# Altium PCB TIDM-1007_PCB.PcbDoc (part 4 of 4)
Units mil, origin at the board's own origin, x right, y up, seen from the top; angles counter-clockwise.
Board outline 9645.67 x 3346.46 mil, 6 copper layers (Top Layer, Signal Layer 1, Signal Layer 2, Signal Layer 3, Signal Layer 4, Bottom Layer), stack 60.2 mil thick; 189 components, 109 nets, 620 pads, 278 vias.
Unrouted connection lines stored in the file: 5.
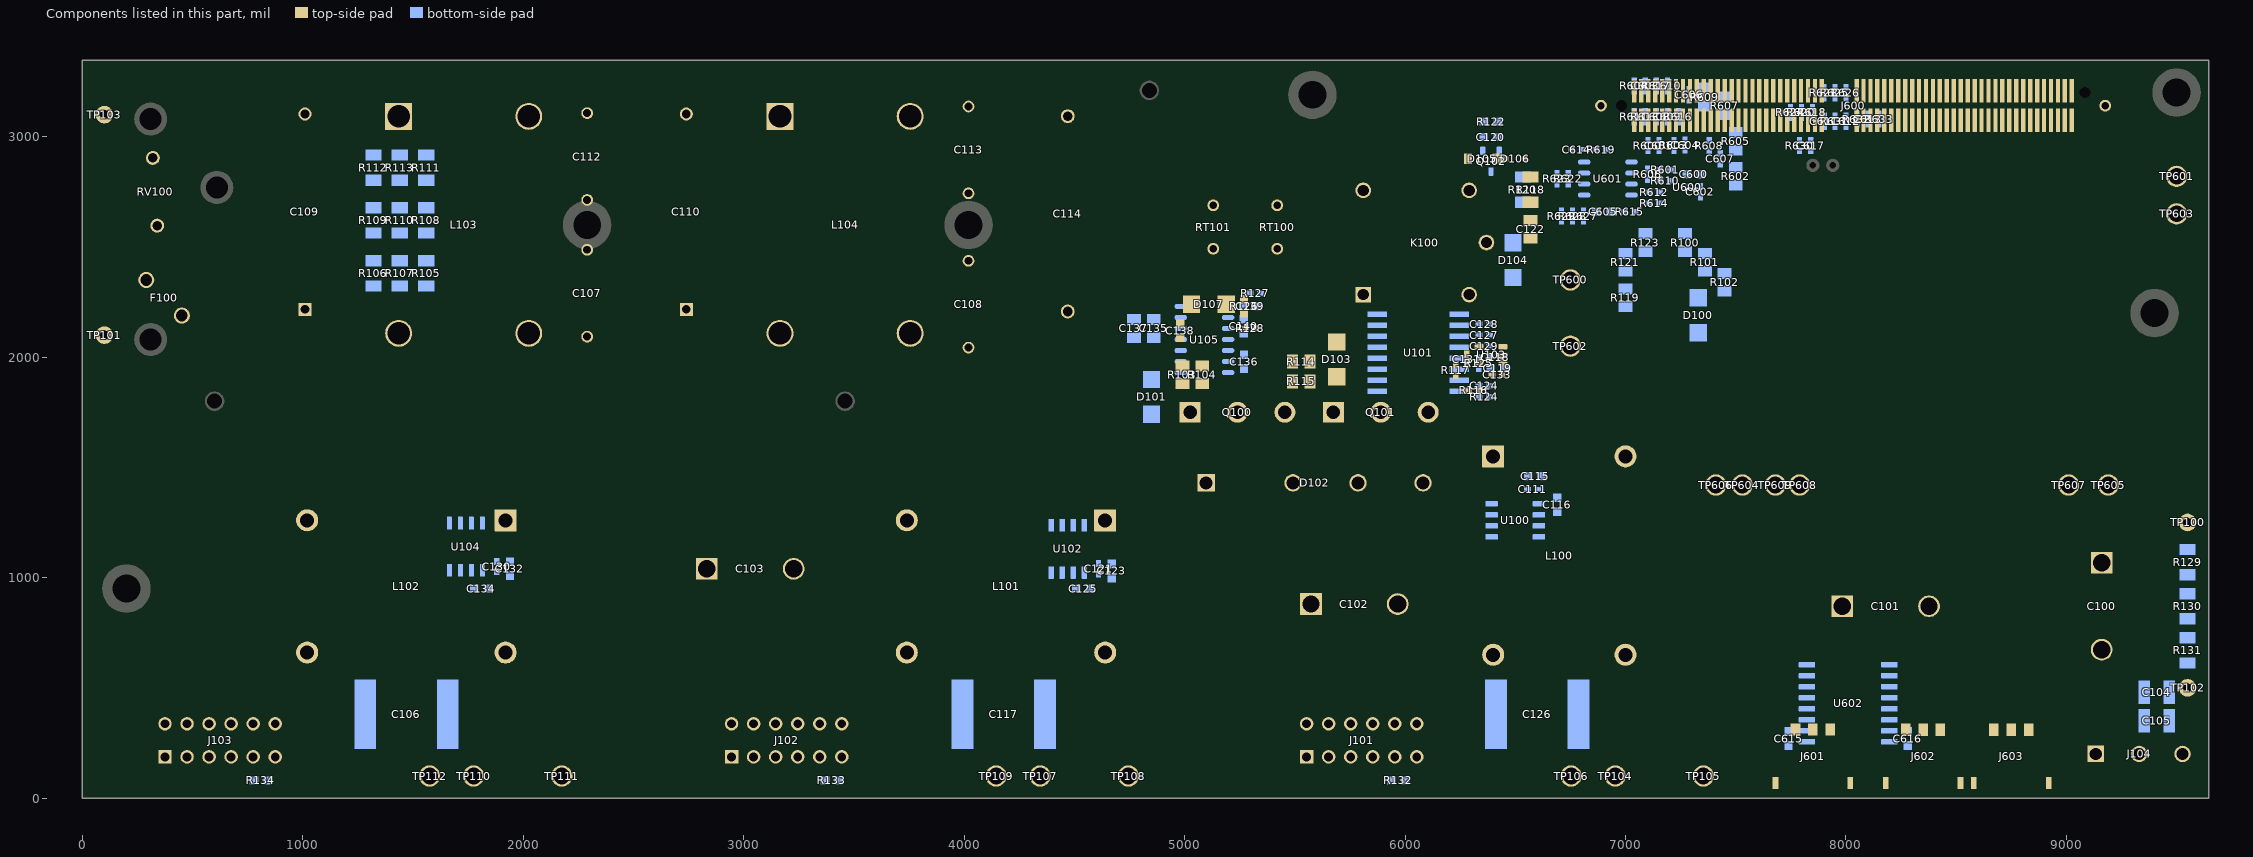
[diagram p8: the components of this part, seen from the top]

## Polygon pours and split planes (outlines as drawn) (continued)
PGND on Signal Layer 4 "PGND" (solid, remove dead copper, pour order 244): 75 vertices, not listed, extent 260,20 9630,3330
NetL102_1 on Signal Layer 4 "L102_1" (solid, remove dead copper, pour order 192): 1770,1200.32 1750,1220.32 1750,1230.32 1750,1260.32 1750,1400 1770,1420 1930,1420 1980,1370 1980,1220.32 1960,1200.32
NetL101_1 on Signal Layer 4 "L101_1" (solid, remove dead copper, pour order 220): 4500,1190 4480,1210 4480,1230 4480,1370 4500,1390 4630,1390 4700,1320 4700,1210 4680,1190
NetL100_1 on Signal Layer 4 "L100_1" (solid, remove dead copper, pour order 228): 6430,1270 6450,1290 6450,1340 6450,1430 6450,1490 6470,1510 6470,1590 6450,1610 6350,1610 6330,1610 6260,1540 6260,1290 6280,1270
SGND2 on Bottom Layer "SGND2" (solid, remove dead copper, pour order 162): 20 vertices, not listed, extent 8160,10 8860,620
NetC109_2 on Bottom Layer "C109_2" (solid, remove dead copper, pour order 16): 20 vertices, not listed, extent 50,2870 1620,3300
NetC110_2 on Bottom Layer "C110_2" (solid, remove dead copper, pour order 22): 1970,3020 1960,3030 1960,3050 1960,3160 2020,3220 2100,3300 2140,3300 3100,3300 3240,3160 3240,3130 3240,3030 3230,3020
-BRDG_N on Bottom Layer "-BRDG_N" (solid, remove dead copper, pour order 64): 29 vertices, not listed, extent 5400,1380 5990,2010
NetF100_2 on Bottom Layer "F100_2" (solid, remove dead copper, pour order 72): 50,2000 110,1940 330,1940 360,1940 500,2080 500,2120 500,2200 470,2230 420,2230 160,2230 50,2120
NetC109_1 on Bottom Layer "C109_1" (solid, remove dead copper, pour order 84): 260.56,2630 140,2509.44 140,2270 160,2250 230,2250 470,2250 580,2140 680,2040 1410,2040 1580,2040 1600,2060 1600,2320 1580,2340 670,2340 380,2630
NetC107_1 on Bottom Layer "C107_1" (solid, remove dead copper, pour order 100): 1960,1950 1970,1940 3230,1940 3240,1950 3240,2130 3100,2270 3050,2270 2550,2270 2460,2180 2270,2180 1970,2180 1960,2170
EARTH on Bottom Layer "Earth" (solid, remove dead copper, pour order 122): 19 vertices, not listed, extent 2140,2390 4140,2800
NetL102_1 on Bottom Layer "L102_1" (solid, remove dead copper, pour order 142): 1770,1200.32 1750,1220.32 1750,1230.32 1750,1260.32 1750,1400 1770,1420 1930,1420 1980,1370 1980,1220.32 1960,1200.32
NetL101_1 on Bottom Layer "L101_1" (solid, remove dead copper, pour order 146): 4500,1190 4480,1210 4480,1230 4480,1370 4500,1390 4630,1390 4700,1320 4700,1210 4680,1190
NetL100_1 on Bottom Layer "L100_1" (solid, remove dead copper, pour order 154): 6430,1270 6450,1290 6450,1340 6450,1430 6450,1490 6470,1510 6470,1590 6450,1610 6350,1610 6330,1610 6260,1540 6260,1290 6280,1270
NetC113_1 on Bottom Layer "C113_2" (solid, remove dead copper, pour order 166): 3700,3020 3690,3030 3690,3060 3690,3160 3830,3300 4405.28,3300 4825.28,2880 5800,2880 5870,2810 5870,2780 5870,2660 5850,2640 5620,2640 4560,2640 4180,3020
AC_L on Bottom Layer "AC_L" (solid, remove dead copper, pour order 176): 66 vertices, not listed, extent 1440,1020 6450,2270
AC_N on Bottom Layer "AC_N" (solid, remove dead copper, pour order 180): 23 vertices, not listed, extent 4870,2030 6410,2620
HVBUS on Bottom Layer "HVBUS" (solid, remove dead copper, pour order 234): 26 vertices, not listed, extent 7820,140 9630,1300
EARTH on Bottom Layer "EARTH" (solid, remove dead copper, pour order 238): 18 vertices, not listed, extent 10,780 670,1850
PGND on Bottom Layer "PGND" (solid, remove dead copper, pour order 242): 64 vertices, not listed, extent 260,20 9630,3330
EARTH on Bottom Layer "EARTH" (solid, remove dead copper, pour order 254): 9290,2740 9290,2070 9310,2050 9620,2050 9640,2070 9640,2090 9640,2470 9640,2740 9620,2760 9310,2760

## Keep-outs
Keep-Out Layer:
  text ".Layer_Name" at 577,-858.49 h60

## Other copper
Top Layer:
  text ".Layer_Name" at 577,-858.49 h60
Bottom Layer:
  text ".Layer_Name" at 577,-858.49 h60

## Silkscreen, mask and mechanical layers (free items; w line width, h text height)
Top Overlay:
  lines w7: 4930,2160 4930,2900 5560,2900 5560,2100 5380,2100 ; 5580,2100 5580,2900 6210,2900 6210,2100 6000,2100 ; 6650,2950 6650,1822.74 7162.26,1822.74 7162.26,1350 9650,1350 9650,2950 8000,2950 ; 6760,2950 7500,2950
  lines w10: 40,1660 130,1660 150,1680 ; 1880,1890 1940,1830 ; 2420,2600 2550,2600 2720,2770 2830,2770 3210,2770 3290,2850 ; 3530,2850 3690,2690 3890,2690 3910,2670 ; 4990,2010 5010,2030 5130,2030 ; 4990,3210 4990,3300 ; 6490,2490 6490,2670 6500,2680 ; 20,1500 20,1830 4810,1830 4810,3320 5090,3320 5090,3300 4830,3300 4830,1810 40,1810 40,1500 20,1500 ; 310,0 2280,0 2280,250 310,250 310,0 ; 2880,0 2880,250 4850,250 4850,0 2880,0 ; 5488.45,-0.23 5488.45,249.77 7458.45,249.77 7458.45,-0.23 5488.45,-0.23
  text "Clearance: L to N >2mm. L/N to PE: 5mm. PGND to SGND: 5mm." at 210,3280 h72.83
  text "Screw / to  / case / here" at 4890,3000 h72.83
  text "Board cutout for Q100 and Q101 clip screw." at 4950,2930 h72.83
  text "Screw to bottom heatsink / #4-40" at 3100,2889.22 h72.83
  text "Grounded Heatsink with 0.5mm thickness." at 60,1870 h100
  text "Reserved for Bias Supply daughter board. No power components on top side." at 7300,1680 h72.83
  text "Screw to case here" at 170,1670 h100
  text ".Layer_Name" at 577,-858.49 h60
Bottom Overlay:
  lines w10: 1080,2640 1240,2640 ; 1890,990 1890,960 1930,920 ; 5380,2220 5420,2180 5430,2180 ; 6510,1960 6600,1960 ; 6610,2570 6610,2680 6670,2740 6680,2740 6690,2750 ; 6650,1410 6690,1410 6710,1430 6760,1430 ; 6660,2570 6660,2700 6680,2720 6720,2720 6740,2740 6740,2750 ; 6670,1460 6690,1460 6720,1490 6750,1490 ; 6690,2030 6600,2030 6600,1890 6810,1890 6830,1890 6830,2030 6810,2030 ; 7340,2660 7390,2610 7620,2610 7750,2480 ; 7900,3150 7920,3150 ; 8200,3070 8340,3070 ; 790,2270 1080,2270 1080,2980 790,2980 790,2870 790,2270 ; 7720,1840 7840,1720 8170,1720 8270,1820 8270,2420 8180,2510 7780,2510 7720,2450 7720,1840 ; 8340,2830 8490,2680 8770,2680 8840,2750 8840,3140 8790,3190 8430,3190 8340,3100 8340,2830
  text ".Layer_Name" at 577,-858.49 h60
Top Paste:
  text ".Layer_Name" at 577,-858.49 h60
Bottom Paste:
  text ".Layer_Name" at 577,-858.49 h60
Top Solder:
  text ".Layer_Name" at 577,-858.49 h60
  text ".Layer_Name" at 577,-858.49 h60
Bottom Solder:
  rectangle: 4950,1150 5300,1290
  rectangle: 4280,1410 4750,1540
  rectangle: 3030,1450 3390,1690
  text ".Layer_Name" at 577,-858.49 h60
Drill Guide:
  text ".Layer_Name" at 577,-858.49 h60
M1 Board Outline:
  the board outline again, w7.01
  text ".Layer_Name" at 577,-858.49 h60
M2 Board Dimensions:
  rectangle: 0,-275 125,-150
  rectangle: 125,-400 500,-275
  lines w7: 0,-275 1000,-275 ; 125,-400 125,-150 ; 250,-400 250,-150 ; 500,-400 500,-150 ; 750,-400 750,-150 ; 0,-400 1000,-400 1000,-150 0,-150 0,-400
  text ".Layer_Name" at 577,-858.49 h60
M3 3D STEP Top:
  text ".Layer_Name" at 577,-858.49 h60
M4 3D STEP Bottom:
  text ".Layer_Name" at 577,-858.49 h60
M5 Assembly Top:
  lines w10: -292,-930.17 6308,-930.17 ; -292,-726.83 6310,-726.83 ; -292,-523.5 -292,-1133.5 3713,-1133.5 6310,-1133.5 6310,-523.5 -291.5,-523.5 -291.5,-1133.5 1284,-1133.5 ; 2173,-1133.5 2173,-523.5 ; 3440,-726.83 3440,-523.5 ; 4280,-726.83 4280,-523.5 ; 4902,-1140 4902,-937.17
  text "COMPONENTS MARKED 'DNP' SHOULD NOT BE POPULATED." at 1153.5,-318.5 h60
  text "ASSEMBLY VARIANT:" at 1153,-434 h60
  text ".VariantName" at 2189,-434 h60
  text "PCB VIEWED FROM TOP SIDE" at -228.5,-655.67 h60
  text "BOARD #:" at 2248,-655.67 h60
  text ".PRJ_Number" at 2793.5,-655.67 h60
  text "REV:" at 3638,-655.67 h60
  text ".PCB_Rev" at 3929.5,-655.67 h60
  text "SVN REV:" at 4476,-655.67 h60
  text ".VersionControl_RevNumber" at 4982,-655.67 h60
  text "TID #:" at 2248,-859 h60
  text ".TID" at 2793.5,-859 h60
  text "PLOT NAME =" at -228.5,-1064.34 h60
  text ".plot_File_Name" at 577,-1064.34 h60
  text "GENERATED    :" at 2250,-1064.34 h60
  text ".Print_Date" at 3119.5,-1064.34 h60
  text ".Print_Time" at 3848.5,-1064.34 h60
  text "TEXAS INSTRUMENTS" at 5113,-1064.34 h60
M6 Assembly Bottom:
  lines w10: -292.5,-727.33 6309.5,-727.33 ; -290.5,-930.67 6309.5,-930.67 ; 1115.5,-1140.5 1115.5,-937.67 ; 1737.5,-727.33 1737.5,-524 ; 2577.5,-727.33 2577.5,-524 ; 3844.5,-1134 3844.5,-524 ; 4733.5,-1134 6309,-1134 6309,-524 -292.5,-524 -292.5,-1134 2304.5,-1134 6309.5,-1134 6309.5,-524
  text "COMPONENTS MARKED 'DNP' SHOULD NOT BE POPULATED." at 6102,-318 h60
  text ".VariantName" at 5058,-434 h60
  text "ASSEMBLY VARIANT:" at 6097,-434 h60
  text ".VersionControl_RevNumber" at 1035.5,-656.17 h60
  text "SVN REV:" at 1541.5,-656.17 h60
  text ".PCB_Rev" at 2088,-656.17 h60
  text "REV:" at 2379.5,-656.17 h60
  text ".PRJ_Number" at 3224,-656.17 h60
  text "BOARD #:" at 3769.5,-656.17 h60
  text "PCB VIEWED FROM BOTTOM SIDE" at 6246,-656.17 h60
  text ".TID" at 3224,-859.5 h60
  text "TID #:" at 3769.5,-859.5 h60
  text "TEXAS INSTRUMENTS" at 904.5,-1064.84 h60
  text ".Print_Time" at 2169,-1064.84 h60
  text ".Print_Date" at 2898,-1064.84 h60
  text "GENERATED    :" at 3767.5,-1064.84 h60
  text ".plot_File_Name" at 5440.5,-1064.84 h60
  text "PLOT NAME =" at 6246,-1064.84 h60
M9 Title Sheet:
  drawing of 57 lines, arcs and shapes, not listed
  text "1" at 739.84,8036.5 h70
  text "2" at 3235.5,8036.5 h70
  text "3" at 5724.84,8036.5 h70
  text "4" at 8231.51,8036.5 h70
  text "5" at 10730.5,8036.5 h70
  text "6" at 13235.5,8036.5 h70
  text "A" at -416.5,6893.5 h70
  text "A" at 14383.5,6893.5 h70
  text "B" at -416.5,4513.5 h70
  text "B" at 14383.5,4513.5 h70
  text "C" at -416.5,2138.5 h70
  text "C" at 14383.5,2138.5 h70
  text "PROJECT TITLE:" at 11343.5,277.5 h45
  text ".PRJ_Title" at 11393.5,144.17 h70
  text "DESIGNED FOR:" at 11343.5,-23.5 h45
  text ".PRJ_Customer" at 11393.5,-163.5 h70
  text "D" at -416.5,-231.5 h70
  text "D" at 14383.5,-231.5 h70
  text "FILE NAME:" at 11343.5,-323.5 h45
  text ".PCB_File_Name_No_Path" at 11393.5,-443.5 h70
  text "Texas Instruments (TI) and/or its licensors do not warrant the accuracy or completeness of this specification" at 6374,-605.34 h45
  text "ENGINEER:" at 11343.5,-613.5 h45
  text "LAYOUT BY:" at 12848.5,-613.5 h45
  text "or any information contained therein. TI and/or its licensors do not warrant that this design will meet" at 6329.01,-718 h45
  text ".PRJ_Engineer" at 11393.5,-768.49 h70
  text ".PCB_Layout" at 12899,-768.49 h70
  text "the specifications, will be suitable for your application or fit for any particular purpose, or will operate in" at 6329.01,-830.67 h45
  text ".Layer_Name" at 577,-858.49 h60
  text "ALTIUM DESIGNER VERSION:" at 12848.5,-923.5 h45
  text "an implementation. TI and/or its licensors do not warrant that the design is production worthy. You should" at 6329.01,-943.33 h45
  text "completely validate and test your design implementation to confirm the system functionality for your application." at 6374,-1056 h45
  text ".print_Scale" at 11393.5,-1056.83 h70
  text ".Application_BuildNumber" at 12899,-1056.83 h70
  text "1" at 739.84,-1263.5 h70
  text "2" at 3235.5,-1263.5 h70
  text "3" at 5724.84,-1263.5 h70
  text "4" at 8231.51,-1263.5 h70
  text "5" at 10730.5,-1263.5 h70
  text "6" at 13235.5,-1263.5 h70
M10 Fab Notes:
  drawing of 173 lines, arcs and shapes, not listed
  text "DESIGN INFORMATION" at 12378.02,6201 h60
  text "MIN. TRACK WIDTH:" at 11733.46,6021 h60
  text "7" at 12829.7,6021 h60
  text "MIL" at 12984.46,6021 h60
  text "MIN. CLEARANCE:" at 11733.46,5889 h60
  text "0.2" at 12769.7,5889 h60
  text "mm" at 12984.46,5889 h60
  text "MIN. VIA PAD SIZE:" at 11733.46,5757 h60
  text "10" at 12799.71,5757 h60
  text "MIL" at 12984.46,5757 h60
  text "0.05mm (2MIL)" at 12428.46,5615.29 h60
  text "MINIMUM ANNULAR RING" at 11404.23,5611 h60
  text "EXTERNAL" at 13136.46,5611 h60
  text "PER" at 11604.23,5493 h60
  text "IPC-D-275 CLASS 2 LEVEL C" at 11824.23,5493 h60
  text "MIL, HOLES" at 13312.46,5380.71 h60
  text "+/-" at 12920,5380 h60
  text "+/-" at 13774,5380 h60
  text "REGISTRATION TOLERANCES:" at 11404.23,5375 h60
  text "METAL" at 12604,5375 h60
  text "5" at 13180.2,5375 h60
  text "3" at 14013.2,5375 h60
  text "MIL" at 14129.46,5375 h60
  text "+/-" at 13774,5262 h60
  text "HOLE SIZE TOLERANCE (UNLESS OTHERWISE SPECIFIED):" at 11404.23,5257 h60
  text "3" at 14013.2,5257 h60
  text "MIL" at 14129.46,5257 h60
  text "MATERIAL:" at 11329.46,5047.54 h60
  text "FR-4 High Tg" at 12315.9,4907.21 h60
  text "FR-408" at 11750.46,4898.64 h60
  text "OTHER" at 13238.46,4898.64 h60
  text "X" at 12161,4895 h60
  text "62 MIL (1.6mm) +/-10%" at 12070.56,4735.92 h60
  text "THICKNESS:" at 11404.23,4731.64 h60
  text "X" at 11942.4,4731.64 h60
  text "OTHER" at 13355.46,4731.64 h60
  text "TOLERANCE:" at 11404.23,4573.64 h60
  text "X" at 12243.53,4573.64 h60
  text "ANSI IPC-6012 TYPE 3 CLASS 2" at 12430.48,4573.64 h60
  text "OTHER +/-" at 12430.46,4417.64 h60
  text "BOW & TWIST:" at 11404.23,4260.64 h60
  text "X" at 12243.53,4260.64 h60
  text "ANSI IPC-6012 TYPE 3 CLASS 2" at 12430.48,4260.64 h60
  text "OTHER +/-" at 12430.46,4102.13 h60
  text "DRILLING:" at 11329.46,3963.64 h60
  text "REFERENCE:" at 11404.23,3846.64 h60
  text "X" at 12052.46,3846.64 h60
  text "AS SHOWN" at 12239.46,3846.64 h60
  text "X" at 12953.46,3846.64 h60
  text "NC_DRILL FILES" at 13090.46,3846.64 h60
  text "PTH COPPER THICKNESS:" at 11404.23,3688.64 h60
  text "X" at 12534.46,3688.64 h60
  text "20-30 um" at 12671.46,3688.64 h60
  text "OTHER" at 13388.46,3688.64 h60
  text "BOARD FINISH:" at 11329.46,3529.64 h60
  text "SILKSCREEN:" at 11484.68,3411.64 h60
  text "X" at 12433.46,3411.64 h60
  text "TOP" at 12559.46,3411.64 h60
  text "X" at 12943.46,3411.64 h60
  text "BOTTOM" at 13070.46,3411.64 h60
  text "SILKSCREEN COLOR:" at 11484.68,3244.64 h60
  text "X" at 12432.42,3244.64 h60
  text "WHITE" at 12559.46,3244.64 h60
  text "OTHER" at 13070.46,3244.64 h60
  text "X" at 12563.42,3085.44 h60
  text "GREEN" at 12690.46,3085.44 h60
  text "OTHER" at 13308.46,3085.44 h60
  text "SOLDER RESIST COLOR:" at 11484.68,3074.64 h60
  text "X" at 12563.42,2915.44 h60
  text "MATTE" at 12690.46,2915.44 h60
  text "SEMI-GLOSS" at 13308,2914.8 h60
  text "IMMERSION GOLD (ENIG)" at 12390.46,2726.92 h60
  text "ENEPIG" at 13728,2723.64 h60
  text "SURFACE FINISH:" at 11329.46,2722.64 h60
  text "IMM. TIN/SILVER OR EQUIV" at 11659,2565.64 h60
  text "OTHER" at 13090.46,2565.64 h60
  text "X" at 11500,2560 h60
  text "ARRAY/PANEL:" at 11329.46,2386.64 h60
  text "CUT AND TRIM PER M1 BOARD OUTLINE" at 12390.46,2382.35 h60
  text "N.C. ROUTE" at 12390.46,2230.64 h60
  text "X" at 13069.46,2230.64 h60
  text "V. SCORE" at 13256.46,2230.64 h60
  text "CERTIFICATION:" at 11329.46,2093.64 h60
  text "MATERIALS AND WORKMANSHIP FOR ALL PCBS" at 12054.46,2093.64 h60
  text "TO MEET OR EXCEED THE REQUIREMENTS OF:" at 12054.46,1995.64 h60
  text "X" at 11680.96,1859.13 h60
  text "ANSI IPC-A-600F CLASS ->" at 11819.96,1859.13 h60
  text "X" at 13459.02,1859.13 h60
  text "2" at 13577.96,1859.14 h60
  text "1" at 13262.96,1857.64 h60
  text "3" at 13931.96,1857.64 h60
  text "X" at 12495.02,1699.64 h60
  text "RoHS" at 12631.96,1699.64 h60
  text "OTHER" at 13276.36,1699.64 h60
  text "PER ORDER" at 13673.42,1699.64 h60
  text "ALL BOARDS MUST MEET OR EXCEED UL94-V0 REQUIREMENTS." at 11357,1534 h60
  text "PCB MUST BEAR THE UL94V-0 UL REGISTERED MATERIAL ID NUMBER" at 11357,1414 h60
  text "ADDITIONAL REQUIREMENTS:" at 11329.46,1240.64 h60
  text "MICROSECTION:" at 11404.23,1125.64 h60
  text "YES" at 12309.96,1125.64 h60
  text "REQUIRED" at 13171.46,969.49 h60
  text "BARE BOARD ELEC. TEST:" at 11404.23,966.64 h60
  text "NONE" at 12709.96,966.64 h60
  text "X" at 13044.46,966.64 h60
  text "PER ORDER" at 13763.46,966.64 h60
  text ".Layer_Name" at 577,-858.49 h60
M11 Gerber Information:
  lines w10: -292,-930.17 6308,-930.17 ; -292,-726.83 6310,-726.83 ; -292,-523.5 -292,-1133.5 3713,-1133.5 6310,-1133.5 6310,-523.5 -291.5,-523.5 -291.5,-1133.5 1284,-1133.5 ; 2173,-1133.5 2173,-523.5 ; 3440,-726.83 3440,-523.5 ; 4280,-726.83 4280,-523.5 ; 4902,-1140 4902,-937.17
  text "ALL ARTWORK VIEWED FROM TOP SIDE" at -228.5,-655.67 h60
  text "BOARD #:" at 2248,-655.67 h60
  text ".PRJ_Number" at 2793.5,-655.67 h60
  text "REV:" at 3638,-655.67 h60
  text ".PCB_Rev" at 3929.5,-655.67 h60
  text "SVN REV:" at 4476,-655.67 h60
  text ".VersionControl_RevNumber" at 4982,-655.67 h60
  text "LAYER NAME =" at -228.5,-858.49 h60
  text "TID #:" at 2248,-859 h60
  text ".TID" at 2793.5,-859 h60
  text "PLOT NAME =" at -228.5,-1064.34 h60
  text ".plot_File_Name" at 577,-1064.34 h60
  text "GENERATED    :" at 2250,-1064.34 h60
  text ".Print_Date" at 3119.5,-1064.34 h60
  text ".Print_Time" at 3848.5,-1064.34 h60
  text "TEXAS INSTRUMENTS" at 5113,-1064.34 h60
M12 Stackup:
  drawing of 399 lines, arcs and shapes, not listed
  text "Layer" at 3260.58,7760 h60
  text "Name" at 3670.49,7760 h60
  text "Material" at 4610.23,7760 h60
  text "Thickness" at 5470,7760 h60
  text "Constant" at 6119.84,7760 h60
  text "Board Layer Stack" at 6689.7,7760 h60
  text "1" at 3260.58,7640 h60
  text "Top Overlay" at 3670.49,7640 h60
  text "2" at 3260.58,7520 h60
  text "Top Solder" at 3670.49,7520 h60
  text "Solder Resist" at 4610.23,7520 h60
  text "0.40mil" at 5470,7520 h60
  text "3.5" at 6119.84,7520 h60
  text "3" at 3260.58,7400 h60
  text "Top Layer" at 3670.49,7400 h60
  text "Copper" at 4610.23,7400 h60
  text "2.80mil" at 5470,7400 h60
  text "4" at 3260.58,7280 h60
  text "Dielectric1" at 3670.49,7280 h60
  text "7.00mil" at 5470,7280 h60
  text "4.2" at 6119.84,7280 h60
  text "5" at 3260.58,7160 h60
  text "Signal Layer 1" at 3670.49,7160 h60
  text "Copper" at 4610.23,7160 h60
  text "1.40mil" at 5470,7160 h60
  text "6" at 3260.58,7040 h60
  text "Dielectric 3" at 3670.49,7040 h60
  text "FR-4" at 4610.23,7040 h60
  text "14.00mil" at 5470,7040 h60
  text "4.2" at 6119.84,7040 h60
  text "7" at 3260.58,6920 h60
  text "Signal Layer 2" at 3670.49,6920 h60
  text "Copper" at 4610.23,6920 h60
  text "1.40mil" at 5470,6920 h60
  text "8" at 3260.58,6800 h60
  text "Dielectric 4" at 3670.49,6800 h60
  text "7.00mil" at 5470,6800 h60
  text "4.2" at 6119.84,6800 h60
  text "9" at 3260.58,6680 h60
  text "Signal Layer 3" at 3670.49,6680 h60
  text "Copper" at 4610.23,6680 h60
  text "1.40mil" at 5470,6680 h60
  text "10" at 3260.58,6560 h60
  text "Dielectric 5" at 3670.49,6560 h60
  text "FR-4" at 4610.23,6560 h60
  text "14.00mil" at 5470,6560 h60
  text "4.2" at 6119.84,6560 h60
  text "11" at 3260.58,6440 h60
  text "Signal Layer 4" at 3670.49,6440 h60
  text "Copper" at 4610.23,6440 h60
  text "1.40mil" at 5470,6440 h60
  text "12" at 3260.58,6320 h60
  text "Dielectric 2" at 3670.49,6320 h60
  text "7.00mil" at 5470,6320 h60
  text "4.2" at 6119.84,6320 h60
  text "13" at 3260.58,6200 h60
  text "Bottom Layer" at 3670.49,6200 h60
  text "Copper" at 4610.23,6200 h60
  text "2.80mil" at 5470,6200 h60
  text "14" at 3260.58,6080 h60
  text "Bottom Solder" at 3670.49,6080 h60
  text "Solder Resist" at 4610.23,6080 h60
  text "0.40mil" at 5470,6080 h60
  text "3.5" at 6119.84,6080 h60
  text "15" at 3260.58,5960 h60
  text "Bottom Overlay" at 3670.49,5960 h60
  text ".Layer_Name" at 577,-858.49 h60
M13 Component Bodies Top:
  text ".Layer_Name" at 577,-858.49 h60
M14 Component Bodies Bottom:
  text ".Layer_Name" at 577,-858.49 h60
M15 Courtyards Top:
  text ".Layer_Name" at 577,-858.49 h60
M16 Courtyards Bottom:
  text ".Layer_Name" at 577,-858.49 h60
Drill Drawing:
  drawing of 184 lines, arcs and shapes, not listed
  text "Symbol" at 60.59,7752.98 h72
  text "Quantity" at 361.16,7752.98 h72
  text "Finished Hole Size" at 693.16,7752.98 h72
  text "Plated" at 1329.72,7752.98 h72
  text "Hole Type" at 1588.86,7752.98 h72
  text "Drill Layer Pair" at 1964.02,7752.98 h72
  text "Tolerance" at 2688.35,7752.98 h72
  text "2" at 361.16,7628.66 h60
  text "1.270mm (50.00mil)" at 693.16,7628.66 h60
  text "NPTH" at 1329.72,7628.66 h60
  text "Round" at 1588.86,7628.66 h60
  text "Top Layer - Bottom Layer" at 1964.02,7628.66 h60
  text "B" at 35.31,7618.67 h55.25
  text "278" at 361.16,7504.34 h60
  text "0.254mm (10.00mil)" at 693.16,7504.34 h60
  text "PTH" at 1329.72,7504.34 h60
  text "Round" at 1588.86,7504.34 h60
  text "Top Layer - Bottom Layer" at 1964.02,7504.34 h60
  text "2" at 361.16,7380.02 h60
  text "0.762mm (30.00mil)" at 693.16,7380.02 h60
  text "PTH" at 1329.72,7380.02 h60
  text "Round" at 1588.86,7380.02 h60
  text "Top Layer - Bottom Layer" at 1964.02,7380.02 h60
  text "2" at 361.16,7255.7 h60
  text "0.840mm (33.07mil)" at 693.16,7255.7 h60
  text "PTH" at 1329.72,7255.7 h60
  text "Round" at 1588.86,7255.7 h60
  text "Top Layer - Bottom Layer" at 1964.02,7255.7 h60
  text "A" at 35.31,7245.7 h55.25
  text "4" at 361.16,7131.38 h60
  text "0.850mm (33.47mil)" at 693.16,7131.38 h60
  text "PTH" at 1329.72,7131.38 h60
  text "Round" at 1588.86,7131.38 h60
  text "Top Layer - Bottom Layer" at 1964.02,7131.38 h60
  text "8" at 361.16,7007.06 h60
  text "0.900mm (35.43mil)" at 693.16,7007.06 h60
  text "PTH" at 1329.72,7007.06 h60
  text "Round" at 1588.86,7007.06 h60
  text "Top Layer - Bottom Layer" at 1964.02,7007.06 h60
  text "4" at 361.16,6882.74 h60
  text "1.000mm (39.37mil)" at 693.16,6882.74 h60
  text "PTH" at 1329.72,6882.74 h60
  text "Round" at 1588.86,6882.74 h60
  text "Top Layer - Bottom Layer" at 1964.02,6882.74 h60
  text "4" at 361.16,6758.42 h60
  text "1.016mm (40.00mil)" at 693.16,6758.42 h60
  text "PTH" at 1329.72,6758.42 h60
  text "Round" at 1588.86,6758.42 h60
  text "Top Layer - Bottom Layer" at 1964.02,6758.42 h60
  text "36" at 361.16,6634.1 h60
  text "1.020mm (40.16mil)" at 693.16,6634.1 h60
  text "PTH" at 1329.72,6634.1 h60
  text "Round" at 1588.86,6634.1 h60
  text "Top Layer - Bottom Layer" at 1964.02,6634.1 h60
  text "F" at 35.31,6624.1 h55.25
  text "4" at 361.16,6509.78 h60
  text "1.100mm (43.31mil)" at 693.16,6509.78 h60
  text "PTH" at 1329.72,6509.78 h60
  text "Round" at 1588.86,6509.78 h60
  text "Top Layer - Bottom Layer" at 1964.02,6509.78 h60
  text "5" at 361.16,6385.46 h60
  text "1.300mm (51.18mil)" at 693.16,6385.46 h60
  text "PTH" at 1329.72,6385.46 h60
  text "Round" at 1588.86,6385.46 h60
  text "Top Layer - Bottom Layer" at 1964.02,6385.46 h60
  text "2" at 361.16,6261.14 h60
  text "1.350mm (53.15mil)" at 693.16,6261.14 h60
  text "PTH" at 1329.72,6261.14 h60
  text "Round" at 1588.86,6261.14 h60
  text "Top Layer - Bottom Layer" at 1964.02,6261.14 h60
  text "3" at 361.16,6136.82 h60
  text "1.400mm (55.12mil)" at 693.16,6136.82 h60
  text "PTH" at 1329.72,6136.82 h60
  text "Round" at 1588.86,6136.82 h60
  text "Top Layer - Bottom Layer" at 1964.02,6136.82 h60
  text "K" at 35.31,6126.82 h55.25
  text "4" at 361.16,6012.5 h60
  text "1.500mm (59.06mil)" at 693.16,6012.5 h60
  text "PTH" at 1329.72,6012.5 h60
  text "Round" at 1588.86,6012.5 h60
  text "Top Layer - Bottom Layer" at 1964.02,6012.5 h60
  text "6" at 361.16,5888.18 h60
  text "1.575mm (62.00mil)" at 693.16,5888.18 h60
  text "PTH" at 1329.72,5888.18 h60
  text "Round" at 1588.86,5888.18 h60
  text "Top Layer - Bottom Layer" at 1964.02,5888.18 h60
  text "12" at 361.16,5763.86 h60
  text "1.613mm (63.50mil)" at 693.16,5763.86 h60
  text "PTH" at 1329.72,5763.86 h60
  text "Round" at 1588.86,5763.86 h60
  text "Top Layer - Bottom Layer" at 1964.02,5763.86 h60
  text "3" at 361.16,5639.54 h60
  text "1.730mm (68.11mil)" at 693.16,5639.54 h60
  text "PTH" at 1329.72,5639.54 h60
  text "Round" at 1588.86,5639.54 h60
  text "Top Layer - Bottom Layer" at 1964.02,5639.54 h60
  text "19" at 361.16,5515.22 h60
  text "1.905mm (75.00mil)" at 693.16,5515.22 h60
  text "PTH" at 1329.72,5515.22 h60
  text "Round" at 1588.86,5515.22 h60
  text "Top Layer - Bottom Layer" at 1964.02,5515.22 h60
  text "M" at 35.31,5505.23 h55.25
  text "8" at 361.16,5390.9 h60
  text "2.000mm (78.74mil)" at 693.16,5390.9 h60
  text "PTH" at 1329.72,5390.9 h60
  text "Round" at 1588.86,5390.9 h60
  text "Top Layer - Bottom Layer" at 1964.02,5390.9 h60
  text "3" at 361.16,5266.58 h60
  text "2.540mm (100.00mil)" at 693.16,5266.58 h60
  text "PTH" at 1329.72,5266.58 h60
  text "Round" at 1588.86,5266.58 h60
  text "Top Layer - Bottom Layer" at 1964.02,5266.58 h60
  text "J" at 35.31,5256.59 h55.25
  text "8" at 361.16,5142.26 h60
  text "2.600mm (102.36mil)" at 693.16,5142.26 h60
  text "PTH" at 1329.72,5142.26 h60
  text "Round" at 1588.86,5142.26 h60
  text "Top Layer - Bottom Layer" at 1964.02,5142.26 h60
  text "6" at 361.16,5017.94 h60
  text "3.200mm (126.00mil)" at 693.16,5017.94 h60
  text "PTH" at 1329.72,5017.94 h60
  text "Round" at 1588.86,5017.94 h60
  text "Top Layer - Bottom Layer" at 1964.02,5017.94 h60
  text "N" at 35.31,5007.94 h55.25
  text "423 Total" at 361.16,4893.62 h60
  text ".Layer_Name" at 577,-858.49 h60
M17 Embedded Cavity:
  text ".Layer_Name" at 577,-858.49 h60
M18 Embedded Assembly:
  text ".Layer_Name" at 577,-858.49 h60
M19 Embedded Keepout:
  text ".Layer_Name" at 577,-858.49 h60

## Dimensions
0,-400 to 1000,-400 on M2 Board Dimensions
0,0 to 0,3346.46 on M2 Board Dimensions
0,0 to 9645.67,0 on M2 Board Dimensions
